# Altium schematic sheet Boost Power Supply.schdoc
size 188 x 106 mm
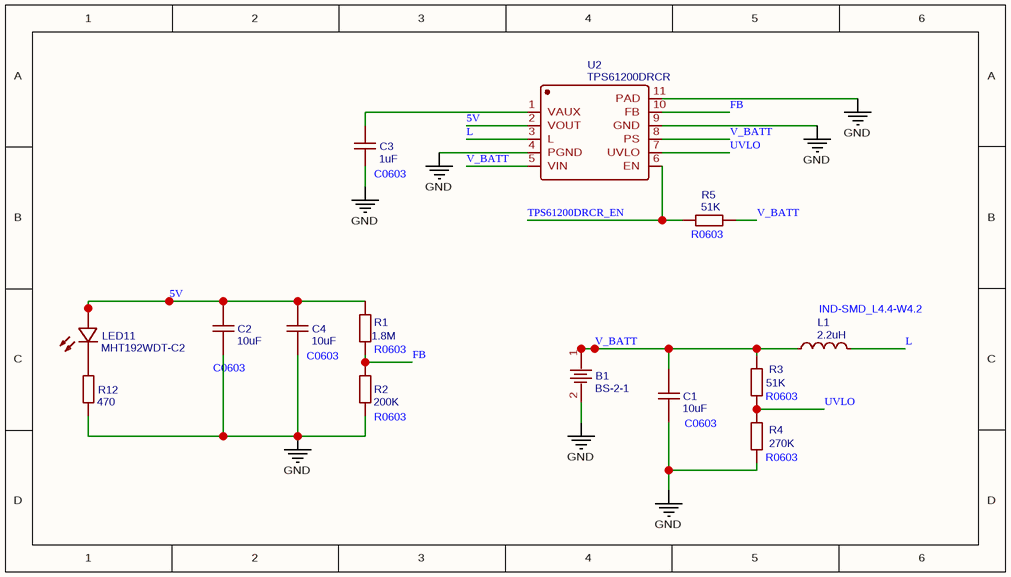
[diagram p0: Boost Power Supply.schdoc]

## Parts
B1  BS-2-1  [KEYSTONE_2466_1XAAA]
C1  10uF  [C0603]
C2  10uF  [C0603]
C3  1uF  [C0603]
C4  10uF  [C0603]
L1  2.2uH  [IND-SMD_L4.4-W4.2]
LED11  MHT192WDT-C2  [LED0603-RD]
R1  1.8M  [R0603]
R2  200K  [R0603]
R3  51K  [R0603]
R4  270K  [R0603]
R5  51K  [R0603]
R12  470  [R0603]
U2  TPS61200DRCR  [VSON-10_L3.0-W3.0-P0.50-BL-EP_TPS62410DRCR]

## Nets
GND: B1.2 C1.1 C2.1 C3.1 C4.1 R2.1 R4.1 R12.1 U2.4(PGND) U2.9(GND) U2.11(PAD)
5V: C2.2 C4.2 LED11.2(+) R1.2 U2.2(VOUT)
FB: R1.1 R2.2 U2.10(FB)
L: L1.2 U2.3(L)
TPS61200DRCR_EN: R5.2 U2.6(EN)
UVLO: R3.1 R4.2 U2.7(UVLO)
V_BATT: B1.1 C1.2 L1.1 R3.2 R5.1 U2.5(VIN) U2.8(PS)
NetC3_2: C3.2 U2.1(VAUX)
NetLED11_1: LED11.1(-) R12.2

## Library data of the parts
B1 = BS-2-1: BOM_Manufacturer: Q&J
C1 C2 C4 = 10uF: BOM_Manufacturer: SAMSUNG; BOM_Manufacturer Part: CL10A106KP8NNNC; nameAlias: Capacitance; SMT Type: Basic; Package Display: Yes
C3 = 1uF: BOM_Manufacturer Part: CL10A105KB8NNNC; BOM_Manufacturer: SAMSUNG; nameAlias: Capacitance; SMT Type: Basic; Package Display: Yes
L1 = 2.2uH: BOM_Manufacturer: Sunlord; BOM_Manufacturer Part: MWSA0402-2R2MT; nameAlias: Inductance; Contributor: LCSC; Package Display: Yes
LED11 = MHT192WDT-C2: BOM_Manufacturer: MEIHUA; Contributor: LCSC
R1 = 1.8M: BOM_Manufacturer: UniOhm; BOM_Manufacturer Part: 0603WAF1804T5E; nameAlias: Resistance (Ohms); SMT Type: Extend; Package Display: Yes
R2 = 200K: BOM_Manufacturer: UniOhm; BOM_Manufacturer Part: 0603WAF2003T5E; nameAlias: Resistance (Ohms); SMT Type: Basic; Package Display: Yes
R3 R5 = 51K: BOM_Manufacturer: UniOhm; BOM_Manufacturer Part: 0603WAF5102T5E; nameAlias: Resistance (Ohms); SMT Type: Basic; Package Display: Yes
R4 = 270K: BOM_Manufacturer: UniOhm; BOM_Manufacturer Part: 0603WAF2703T5E; nameAlias: Resistance (Ohms); SMT Type: Basic; Package Display: Yes
R12 = 470: BOM_Manufacturer: UniOhm; BOM_Manufacturer Part: 0603WAF4700T5E; nameAlias: Resistance (Ohms); SMT Type: Basic
U2 = TPS61200DRCR: BOM_Manufacturer: Texas Instruments; Contributor: LCSC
